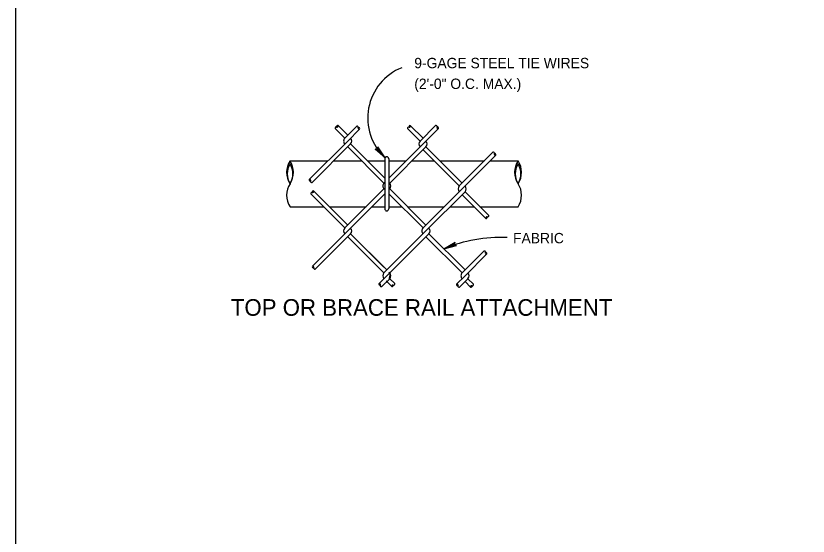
# Model space of a CAD drawing. Extents: x -123486 to -116575, y -107066 to -101122.
# Drawn here: x -119542.4 to -119083.8, y -101724.4 to -101423.4 of the extents above; entities that cross this region are included whole.
import ezdxf

# ---------------------------------------------------------------- set-up
doc = ezdxf.new("R2010")
doc.units = 0
doc.layers.add('Default', color=7, linetype='Continuous')
doc.layers.add('G-MARK', color=7, linetype='Continuous')

msp = doc.modelspace()

# ---------------------------------------------------------------- linework, layer by layer
at = {"layer": 'Default'}
msp.add_lwpolyline([(-119542.38, -101122.36), (-117742.38, -101122.36), (-117742.38, -102572.36), (-119542.38, -102572.36)], close=True, dxfattribs=at)
at = {"layer": 'G-MARK'}
for p, q in [((-119357.61, -101488.52), (-119351.98, -101494.15)), ((-119355.93, -101486.85), (-119350.31, -101492.48)), ((-119351.98, -101494.15), (-119345.08, -101487.24)), ((-119350.31, -101495.82), (-119343.4, -101488.92)), ((-119315.63, -101488.59), (-119308.4, -101495.83)), ((-119313.96, -101486.91), (-119306.72, -101494.15)), ((-119308.4, -101495.83), (-119299.44, -101486.87)), ((-119306.73, -101497.5), (-119297.77, -101488.54)), ((-119372.59, -101518.11), (-119350.31, -101495.82)), ((-119370.92, -101519.79), (-119348.63, -101497.5)), ((-119350.31, -101499.17), (-119329.35, -101520.13)), ((-119348.63, -101497.5), (-119328.9, -101517.23)), ((-119328.73, -101505.46), (-119332.82, -101499.07)), ((-119326.53, -101517.3), (-119306.73, -101497.5)), ((-119326.53, -101520.65), (-119305.05, -101499.17)), ((-119305.05, -101499.17), (-119284.1, -101520.13)), ((-119305.05, -101499.17), (-119284.1, -101520.12)), ((-119328.73, -101505.46), (-119334.46, -101500.5)), ((-119328.73, -101505.46), (-119333.97, -101500.6)), ((-119328.73, -101505.46), (-119333.63, -101500.59)), ((-119328.73, -101505.46), (-119333.36, -101500.51)), ((-119328.73, -101505.46), (-119333.24, -101500.25)), ((-119328.73, -101505.46), (-119333.14, -101500.37)), ((-119328.73, -101505.46), (-119332.99, -101500.22)), ((-119328.73, -101505.46), (-119332.86, -101499.97)), ((-119328.73, -101505.46), (-119332.79, -101499.64)), ((-119306.73, -101500.85), (-119285.77, -101521.8)), ((-119306.73, -101546.1), (-119264.59, -101503.97)), ((-119285.77, -101521.8), (-119266.27, -101502.3)), ((-119383.71, -101507.24), (-119361.73, -101507.24)), ((-119358.38, -101507.24), (-119342.24, -101507.24)), ((-119338.89, -101507.24), (-119328.9, -101507.24)), ((-119328.9, -101506.06), (-119328.9, -101534.99)), ((-119326.53, -101506.06), (-119326.53, -101534.99)), ((-119326.53, -101507.24), (-119316.47, -101507.24)), ((-119313.12, -101507.24), (-119300.33, -101507.24)), ((-119296.98, -101507.24), (-119271.22, -101507.24)), ((-119267.87, -101507.24), (-119251.71, -101507.24)), ((-119372.59, -101518.11), (-119367.71, -101513.22)), ((-119329.35, -101520.13), (-119328.9, -101519.67)), ((-119371.67, -101526.41), (-119351.98, -101546.1)), ((-119370.79, -101568.26), (-119328.9, -101526.37)), ((-119370, -101524.74), (-119350.3, -101544.43)), ((-119351.98, -101546.1), (-119329.35, -101523.47)), ((-119329.35, -101523.47), (-119328.9, -101523.02)), ((-119326.53, -101524), (-119326.01, -101523.47)), ((-119326.53, -101526.3), (-119306.73, -101546.1)), ((-119326.53, -101526.3), (-119306.73, -101546.1)), ((-119326, -101523.48), (-119305.05, -101544.43)), ((-119305.05, -101547.78), (-119282.42, -101525.15)), ((-119284.1, -101526.82), (-119270.41, -101540.51)), ((-119282.42, -101525.15), (-119268.73, -101538.84)), ((-119383.71, -101533.8), (-119364.28, -101533.8)), ((-119360.93, -101533.8), (-119339.68, -101533.8)), ((-119336.33, -101533.8), (-119328.9, -101533.8)), ((-119326.53, -101533.8), (-119319.02, -101533.8)), ((-119315.68, -101533.8), (-119294.43, -101533.8)), ((-119291.08, -101533.8), (-119277.12, -101533.8)), ((-119273.77, -101533.8), (-119251.71, -101533.8)), ((-119369.12, -101569.93), (-119348.63, -101549.45)), ((-119350.31, -101547.77), (-119350.31, -101547.77)), ((-119348.63, -101549.45), (-119327.68, -101570.4)), ((-119348.63, -101549.45), (-119327.68, -101570.4)), ((-119348.63, -101549.45), (-119329.35, -101568.73)), ((-119332.24, -101578.31), (-119303.38, -101549.45)), ((-119329.35, -101572.08), (-119305.05, -101547.78)), ((-119303.38, -101549.45), (-119282.42, -101570.4)), ((-119350.31, -101551.12), (-119329.35, -101572.08)), ((-119305.05, -101551.13), (-119284.1, -101572.08)), ((-119294.71, -101558.12), (-119288.16, -101554.3)), ((-119294.71, -101558.12), (-119288.42, -101554.74)), ((-119294.71, -101558.12), (-119288.51, -101555.06)), ((-119294.71, -101558.12), (-119288.53, -101555.34)), ((-119294.71, -101558.12), (-119288.47, -101555.6)), ((-119294.71, -101558.12), (-119288.37, -101555.79)), ((-119294.71, -101558.12), (-119288.18, -101555.99)), ((-119294.71, -101558.12), (-119287.89, -101556.17)), ((-119294.71, -101558.12), (-119287.34, -101556.31)), ((-119284.1, -101572.08), (-119271.47, -101559.45)), ((-119282.42, -101573.75), (-119269.8, -101561.12)), ((-119330.57, -101579.99), (-119326, -101575.42)), ((-119328.05, -101576.72), (-119324.81, -101579.97)), ((-119327.68, -101577.1), (-119324.81, -101579.97)), ((-119326.38, -101575.05), (-119323.14, -101578.29)), ((-119326, -101575.42), (-119323.14, -101578.29)), ((-119287.31, -101578.64), (-119282.42, -101573.75)), ((-119285.64, -101580.31), (-119280.75, -101575.43)), ((-119282.42, -101577.1), (-119279.18, -101580.34)), ((-119280.75, -101575.43), (-119277.5, -101578.67))]:
    msp.add_line(p, q, dxfattribs=at)
for points in [[(-119332.82, -101499.07), (-119332.79, -101499.64), (-119332.86, -101499.97), (-119332.99, -101500.22), (-119333.16, -101500.39), (-119333.36, -101500.51), (-119333.63, -101500.59), (-119333.97, -101500.6), (-119334.46, -101500.5)], [(-119287.34, -101556.31), (-119287.89, -101556.17), (-119288.18, -101555.99), (-119288.37, -101555.79), (-119288.48, -101555.57), (-119288.53, -101555.34), (-119288.51, -101555.06), (-119288.42, -101554.74), (-119288.16, -101554.3)]]:
    msp.add_lwpolyline(points, dxfattribs=at)
for centre, radius, start, end in [((-119307.36, -101482.47), 31.38, 111.856, 227.0802), ((-119357.02, -101488.27), 0.638, 66.865, 203.1351), ((-119356.18, -101487.44), 0.638, 66.865, 203.1351), ((-119356.52, -101487.1), 0.638, 246.9589, 23.041), ((-119344.83, -101487.83), 0.638, 336.865, 113.1351), ((-119343.65, -101488.33), 0.638, 156.9589, 293.0411), ((-119343.99, -101488.67), 0.638, 336.865, 113.1351), ((-119315.05, -101488.34), 0.638, 66.865, 203.1351), ((-119314.21, -101487.5), 0.638, 66.865, 203.1351), ((-119314.55, -101487.16), 0.638, 246.9589, 23.041), ((-119299.19, -101487.46), 0.638, 336.865, 113.1351), ((-119298.02, -101487.96), 0.638, 156.9589, 293.0411), ((-119298.36, -101488.29), 0.638, 336.865, 113.1351), ((-119350.31, -101495.82), 2.37, 135, 225.0685), ((-119350.31, -101495.82), 2.37, 315, 45), ((-119306.73, -101497.5), 2.36, 135, 225), ((-119306.73, -101497.5), 2.37, 315, 44.9315), ((-119266.02, -101502.88), 0.638, 336.865, 113.1351), ((-119264.84, -101503.38), 0.638, 156.9589, 293.0411), ((-119265.18, -101503.72), 0.638, 336.865, 113.1351), ((-119373.69, -101513.88), 12.02, 146.4749, 213.5251), ((-119393.74, -101513.88), 12.02, 326.4749, 33.5251), ((-119327.71, -101506.06), 1.18, 0, 180), ((-119241.69, -101513.88), 12.02, 146.4749, 213.5251), ((-119261.74, -101513.88), 12.02, 326.4749, 33.5251), ((-119374.23, -101514.77), 11.09, 148.7514, 211.2486), ((-119392.8, -101514.77), 10.76, 327.6715, 32.3285), ((-119242.62, -101514.77), 10.76, 147.6715, 212.3285), ((-119261.19, -101514.77), 11.09, 328.7514, 31.2486), ((-119373.69, -101527.16), 12.02, 146.4749, 213.5251), ((-119372.01, -101518.36), 0.638, 156.865, 293.1351), ((-119372.34, -101518.7), 0.638, 336.9589, 113.0411), ((-119371.17, -101519.2), 0.638, 156.865, 293.1351), ((-119327.68, -101521.8), 2.37, 135, 225.0685), ((-119327.68, -101521.8), 2.37, 315, 45), ((-119284.1, -101523.47), 2.37, 135, 225), ((-119284.1, -101523.47), 2.37, 315, 45), ((-119261.74, -101527.16), 12.02, 326.4749, 33.5251), ((-119371.09, -101526.16), 0.638, 66.865, 203.1351), ((-119370.25, -101525.32), 0.638, 66.865, 203.1351), ((-119370.58, -101524.99), 0.638, 246.9589, 23.041), ((-119327.71, -101534.99), 1.18, 180, 0), ((-119269.82, -101540.26), 0.638, 66.9589, 203.0411), ((-119270.16, -101539.93), 0.638, 246.8649, 23.135), ((-119269.32, -101539.09), 0.638, 246.8649, 23.135), ((-119350.31, -101547.78), 2.36, 135, 225), ((-119350.31, -101547.78), 2.37, 315, 44.9315), ((-119305.05, -101547.78), 2.37, 135, 225.0685), ((-119305.05, -101547.78), 2.37, 315, 45), ((-119261.69, -101637.95), 86.39, 87.5713, 112.4665), ((-119271.22, -101560.04), 0.638, 336.865, 113.1351), ((-119270.05, -101560.54), 0.638, 156.9589, 293.0411), ((-119270.38, -101560.87), 0.638, 336.865, 113.1351), ((-119370.2, -101568.51), 0.638, 156.865, 293.1351), ((-119370.54, -101568.85), 0.638, 336.9589, 113.0411), ((-119369.37, -101569.35), 0.638, 156.865, 293.1351), ((-119327.68, -101573.75), 2.37, 135, 225), ((-119328.05, -101573.37), 2.37, 315, 45), ((-119327.68, -101573.75), 2.37, 315, 45), ((-119282.42, -101573.75), 2.37, 135, 225.0685), ((-119282.42, -101573.75), 2.37, 315, 45), ((-119331.66, -101578.57), 0.638, 156.865, 293.1351), ((-119331.99, -101578.9), 0.638, 336.9589, 113.0411), ((-119330.82, -101579.4), 0.638, 156.865, 293.1351), ((-119324.22, -101579.72), 0.638, 66.9589, 203.0411), ((-119324.56, -101579.38), 0.638, 246.8649, 23.135), ((-119323.72, -101578.55), 0.638, 246.8649, 23.135), ((-119286.72, -101578.89), 0.638, 156.865, 293.1351), ((-119287.06, -101579.23), 0.638, 336.9589, 113.0411), ((-119285.89, -101579.73), 0.638, 156.865, 293.1351), ((-119278.59, -101580.1), 0.638, 66.9589, 203.0411), ((-119278.93, -101579.76), 0.638, 246.8649, 23.135), ((-119278.09, -101578.92), 0.638, 246.8649, 23.135)]:
    msp.add_arc(centre, radius, start, end, dxfattribs=at)

# ---------------------------------------------------------------- texts
for s, height, p in [('9-GAGE STEEL TIE WIRES', 6, (-119311.79, -101453.67)), ('(2\'-0" O.C. MAX.) ', 6, (-119311.79, -101465.67)), ('FABRIC', 6, (-119254.64, -101554.96)), ('TOP OR BRACE RAIL ATTACHMENT', 9.618, (-119417.96, -101596.89))]:
    msp.add_text(s, height=height, dxfattribs=at).set_placement(p)

doc.saveas('drawing.dxf')
